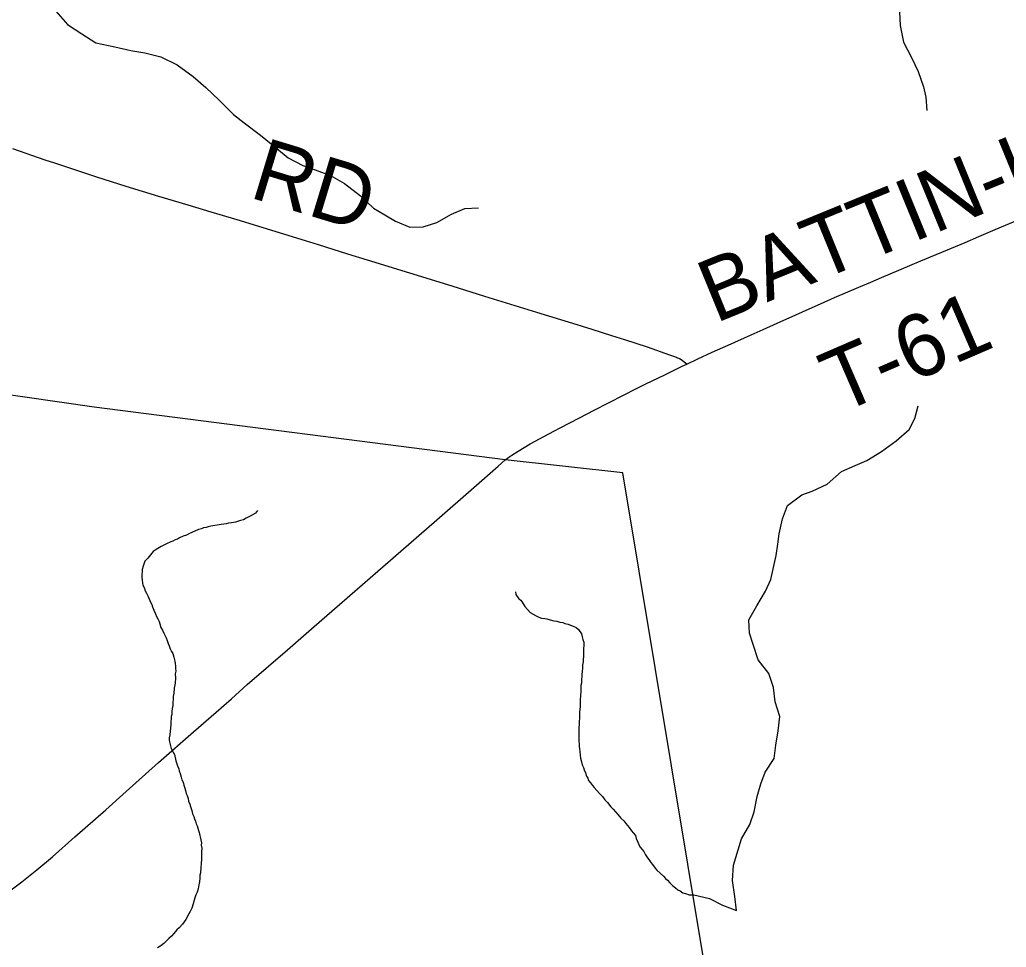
# Model space of a CAD drawing. Extents: x -19.5 to 44.1, y 0 to 22.
# Drawn here: x -14.727 to -13.829, y 6.591 to 7.436 of the extents above; entities that cross this region are included whole.
import ezdxf

# ---------------------------------------------------------------- set-up
doc = ezdxf.new("R2010")
doc.units = 0
for name, color, linetype in [('GM_X_County_Road', 7, 'Continuous'), ('GM_X_Minor_River', 7, 'Continuous'), ('GM_X_Township', 7, 'Continuous'), ('GM_X_Township_Road', 7, 'Continuous'), ('GM_X_Township_Road_Text', 7, 'Continuous')]:
    doc.layers.add(name, color=color, linetype=linetype)

msp = doc.modelspace()

# ---------------------------------------------------------------- linework, layer by layer
at = {"layer": 'GM_X_County_Road'}
msp.add_lwpolyline([(-14.7407, 6.63925), (-14.72466, 6.65093), (-14.71108, 6.66173), (-14.69691, 6.67379), (-14.67641, 6.69188), (-14.64848, 6.71653), (-14.62991, 6.73303), (-14.60029, 6.75953), (-14.56866, 6.78754), (-14.54805, 6.80551), (-14.53392, 6.81759), (-14.51956, 6.83042), (-14.48296, 6.86218), (-14.45863, 6.88343), (-14.43562, 6.90338), (-14.3868, 6.94571), (-14.347, 6.9804), (-14.31342, 7.00997), (-14.2913, 7.02939), (-14.28499, 7.03495)], dxfattribs=at)
at = {"layer": 'GM_X_Minor_River'}
for points in [[(-14.69382, 7.44333), (-14.68334, 7.43108), (-14.67016, 7.4226), (-14.65736, 7.4145)], [(-13.92594, 7.44273), (-13.92531, 7.4302), (-13.92242, 7.415), (-13.91496, 7.40126), (-13.90902, 7.3883), (-13.90422, 7.3746), (-13.90203, 7.36509), (-13.90101, 7.35294)], [(-14.65736, 7.4145), (-14.6401, 7.41099), (-14.62569, 7.4075), (-14.6128, 7.40547), (-14.59841, 7.40192), (-14.5833, 7.39456), (-14.56897, 7.3838), (-14.5573, 7.37382), (-14.54526, 7.36232), (-14.5321, 7.34929), (-14.52231, 7.3416), (-14.50761, 7.33046), (-14.49292, 7.31855), (-14.48237, 7.30972), (-14.46915, 7.30276), (-14.4578, 7.29885), (-14.4438, 7.29379), (-14.43097, 7.28645), (-14.41665, 7.27531), (-14.40461, 7.26419), (-14.39441, 7.25801), (-14.3846, 7.25223), (-14.37174, 7.24679), (-14.35959, 7.24705), (-14.34702, 7.2511), (-14.33366, 7.25855), (-14.32146, 7.26375), (-14.3093, 7.26439)], [(-14.11323, 6.6392), (-14.09906, 6.63563), (-14.08697, 6.62982), (-14.07449, 6.62477), (-14.07588, 6.63768), (-14.07802, 6.65211), (-14.07712, 6.66614), (-14.07281, 6.68013), (-14.06967, 6.68997), (-14.06233, 6.70317), (-14.05842, 6.71451), (-14.05562, 6.72852), (-14.05209, 6.74024), (-14.04819, 6.75083), (-14.0401, 6.76326), (-14.03846, 6.77539), (-14.03643, 6.78826), (-14.03478, 6.80152), (-14.03921, 6.81484), (-14.0406, 6.82776), (-14.04503, 6.8407), (-14.05478, 6.85293), (-14.0592, 6.86701), (-14.06251, 6.87729), (-14.06315, 6.88943), (-14.05581, 6.90226), (-14.04809, 6.91546), (-14.04305, 6.92603), (-14.03828, 6.94798), (-14.03666, 6.95821), (-14.03542, 6.96768), (-14.03263, 6.98131), (-14.02796, 6.9934), (-14.01495, 7.00314), (-14.00543, 7.00646), (-13.99169, 7.01277), (-13.97867, 7.0244), (-13.96647, 7.02998), (-13.95579, 7.03442), (-13.94242, 7.04264), (-13.92904, 7.05237), (-13.91716, 7.06249), (-13.91213, 7.07269), (-13.90898, 7.08404)], [(-14.5103, 6.98897), (-14.51224, 6.98634), (-14.51686, 6.98376), (-14.52069, 6.98193), (-14.523, 6.98044), (-14.52568, 6.97973), (-14.52836, 6.97902), (-14.53027, 6.97829), (-14.53218, 6.97794), (-14.53409, 6.97759), (-14.53676, 6.97726), (-14.53868, 6.97691), (-14.54097, 6.97657), (-14.54326, 6.97623), (-14.54517, 6.97588), (-14.54708, 6.97554), (-14.54899, 6.97519), (-14.5509, 6.97484), (-14.5528, 6.9745), (-14.5551, 6.97415), (-14.55701, 6.97343), (-14.5593, 6.97309), (-14.56122, 6.97236), (-14.56389, 6.97165), (-14.56735, 6.97019), (-14.57233, 6.96799), (-14.57502, 6.96652), (-14.57809, 6.96543), (-14.58116, 6.96396), (-14.58308, 6.96285), (-14.58538, 6.96213), (-14.5873, 6.96103), (-14.58922, 6.9603), (-14.59305, 6.95847), (-14.59497, 6.95774), (-14.59804, 6.95627), (-14.60112, 6.95442), (-14.60343, 6.95294), (-14.60536, 6.95146), (-14.60769, 6.94846), (-14.61003, 6.94546), (-14.61273, 6.94284), (-14.61353, 6.94095), (-14.61433, 6.93831), (-14.61515, 6.93528), (-14.61518, 6.933), (-14.6156, 6.93073), (-14.61565, 6.92807), (-14.6153, 6.92578), (-14.61497, 6.92274), (-14.61462, 6.92083), (-14.61351, 6.91891), (-14.61242, 6.91585), (-14.61132, 6.91355), (-14.60985, 6.91049), (-14.60764, 6.90551), (-14.60654, 6.90321), (-14.60581, 6.9013), (-14.60472, 6.89824), (-14.60325, 6.89479), (-14.60215, 6.8925), (-14.60105, 6.8902), (-14.59994, 6.8879), (-14.59922, 6.88561), (-14.59813, 6.88254), (-14.59665, 6.87986), (-14.59555, 6.87718), (-14.59444, 6.87488), (-14.59333, 6.87296), (-14.59261, 6.87067), (-14.59151, 6.86799), (-14.59079, 6.8657), (-14.58969, 6.86302), (-14.58859, 6.86072), (-14.58748, 6.8588), (-14.58639, 6.85536), (-14.58569, 6.85193), (-14.58535, 6.84964), (-14.585, 6.84736), (-14.58504, 6.84508), (-14.5847, 6.84279), (-14.58512, 6.84014), (-14.5848, 6.83671), (-14.58526, 6.83178), (-14.5861, 6.82724), (-14.58655, 6.82268), (-14.58699, 6.81965), (-14.58702, 6.81737), (-14.58746, 6.81396), (-14.58751, 6.8113), (-14.58793, 6.80865), (-14.58836, 6.80599), (-14.5884, 6.80333), (-14.58881, 6.80144), (-14.58885, 6.79916), (-14.58927, 6.79689), (-14.58931, 6.79423), (-14.59023, 6.78474), (-14.59066, 6.78209), (-14.59069, 6.78019), (-14.59034, 6.77829)], [(-14.27544, 6.91501), (-14.2751, 6.91235), (-14.2725, 6.9085), (-14.27061, 6.90733), (-14.2695, 6.90541), (-14.2669, 6.90156), (-14.26466, 6.89887), (-14.26204, 6.89616), (-14.2594, 6.89459), (-14.25676, 6.89303), (-14.25412, 6.89184), (-14.25184, 6.89104), (-14.2488, 6.89061), (-14.24691, 6.8902), (-14.24387, 6.88939), (-14.24046, 6.88857), (-14.2378, 6.88814), (-14.23515, 6.88734), (-14.23249, 6.88691), (-14.2306, 6.88612), (-14.22757, 6.88531), (-14.2253, 6.88451), (-14.22302, 6.88371), (-14.22038, 6.88252), (-14.21812, 6.88058), (-14.21552, 6.87674), (-14.21481, 6.87407), (-14.21409, 6.8714), (-14.21337, 6.8691), (-14.21342, 6.86606), (-14.21347, 6.86302), (-14.21352, 6.85961), (-14.21356, 6.85771), (-14.21359, 6.85581), (-14.21401, 6.85353), (-14.21405, 6.85125), (-14.21448, 6.84822), (-14.21453, 6.84518), (-14.21495, 6.84253), (-14.215, 6.83949), (-14.21503, 6.83759), (-14.21545, 6.83569), (-14.21551, 6.8319), (-14.21593, 6.82962), (-14.21596, 6.82772), (-14.216, 6.82544), (-14.21603, 6.82354), (-14.21645, 6.82127), (-14.21648, 6.81937), (-14.21651, 6.81747), (-14.21654, 6.81557), (-14.21659, 6.81253), (-14.21663, 6.81025), (-14.21705, 6.80798), (-14.21709, 6.80532), (-14.21713, 6.80304), (-14.21718, 6.8), (-14.21761, 6.79697), (-14.21775, 6.78861), (-14.2178, 6.78595), (-14.21785, 6.78253), (-14.21788, 6.78063), (-14.21792, 6.77873), (-14.21757, 6.77683), (-14.21761, 6.77417), (-14.21727, 6.77188), (-14.21693, 6.7696), (-14.2166, 6.76617), (-14.21627, 6.76351), (-14.21556, 6.76007), (-14.21484, 6.7574), (-14.21374, 6.7551), (-14.21302, 6.75281), (-14.21192, 6.75013), (-14.21083, 6.74707), (-14.20972, 6.74515), (-14.20899, 6.74324), (-14.20712, 6.74093), (-14.20526, 6.73862), (-14.20376, 6.73669), (-14.20152, 6.73399), (-14.19891, 6.73129), (-14.19628, 6.72858), (-14.19405, 6.7255), (-14.1918, 6.72318), (-14.18882, 6.71933), (-14.18658, 6.71701), (-14.18246, 6.71238), (-14.17948, 6.70891), (-14.17685, 6.70659), (-14.17499, 6.7039), (-14.172, 6.70042), (-14.16977, 6.69734), (-14.16828, 6.69542), (-14.16641, 6.69311), (-14.16569, 6.69043), (-14.16423, 6.68699), (-14.16239, 6.68278), (-14.16015, 6.68046), (-14.15866, 6.67853), (-14.15718, 6.67547)], [(-14.59034, 6.77829), (-14.58963, 6.77485), (-14.58892, 6.77218), (-14.58706, 6.76911), (-14.58596, 6.76681), (-14.58453, 6.76108), (-14.58308, 6.7565), (-14.58199, 6.75382), (-14.58164, 6.75191), (-14.58054, 6.74962), (-14.57983, 6.74618), (-14.57911, 6.74389), (-14.578, 6.74159), (-14.57729, 6.73892), (-14.57657, 6.73625), (-14.57584, 6.73395), (-14.57513, 6.73128), (-14.5744, 6.72937), (-14.5733, 6.72669), (-14.57296, 6.7244), (-14.57186, 6.72172), (-14.57114, 6.71943), (-14.57005, 6.71599), (-14.56934, 6.71294), (-14.56824, 6.71026), (-14.56751, 6.70835), (-14.56679, 6.70606), (-14.56607, 6.70376), (-14.56534, 6.70185), (-14.56461, 6.69994), (-14.56388, 6.69765), (-14.56353, 6.69574), (-14.56174, 6.68925), (-14.5614, 6.68658), (-14.56144, 6.6843), (-14.5611, 6.68164), (-14.56116, 6.67822), (-14.5612, 6.67594), (-14.56124, 6.67366), (-14.56127, 6.67138), (-14.56171, 6.66797), (-14.56178, 6.66379), (-14.56224, 6.65924), (-14.56266, 6.65696), (-14.5627, 6.65431), (-14.56314, 6.65089), (-14.56356, 6.64824), (-14.56439, 6.64445), (-14.5652, 6.64143), (-14.56638, 6.63917), (-14.56719, 6.63652), (-14.5688, 6.63085), (-14.57001, 6.62707), (-14.57158, 6.62406), (-14.57276, 6.62179), (-14.57551, 6.61652), (-14.57863, 6.6124), (-14.58173, 6.60903), (-14.58367, 6.60716), (-14.58639, 6.60379), (-14.58871, 6.60155), (-14.59103, 6.59931), (-14.59335, 6.59707), (-14.59568, 6.59483), (-14.59838, 6.59259), (-14.60146, 6.59075)], [(-14.15718, 6.67547), (-14.15607, 6.67355), (-14.15346, 6.67046), (-14.15235, 6.66854), (-14.15086, 6.66662), (-14.14824, 6.66353), (-14.14675, 6.66161), (-14.14375, 6.6589), (-14.14075, 6.65619), (-14.13888, 6.65387), (-14.13701, 6.65232), (-14.13514, 6.65001), (-14.13251, 6.64768), (-14.12989, 6.64536), (-14.12763, 6.6438), (-14.12574, 6.64263), (-14.1231, 6.64106), (-14.12083, 6.64026), (-14.11743, 6.63906), (-14.11323, 6.6392)]]:
    msp.add_lwpolyline(points, dxfattribs=at)
at = {"layer": 'GM_X_Township'}
msp.add_lwpolyline([(-12.89135, 6.37944), (-13.11367, 6.40414), (-13.35833, 6.42942), (-13.44114, 6.43455), (-13.5998, 6.44439), (-14.08907, 6.4899), (-14.17771, 7.02314), (-14.28499, 7.03495), (-14.65899, 7.08304), (-15.5678, 7.21413), (-15.56001, 7.19629), (-16.11933, 6.86064), (-16.1939, 6.81589), (-16.21334, 6.81208), (-16.897, 6.44106), (-17.1473, 6.30523)], dxfattribs=at)
at = {"layer": 'GM_X_Township_Road'}
for points in [[(-14.1197, 7.12209), (-14.12199, 7.12392), (-14.1239, 7.12543), (-14.12637, 7.12698), (-14.13053, 7.12871), (-14.1349, 7.13035), (-14.15543, 7.13741), (-14.17604, 7.1442), (-14.18784, 7.14795), (-14.20562, 7.1535), (-14.22341, 7.15901), (-14.25603, 7.16907), (-14.30348, 7.18378), (-14.3331, 7.19297), (-14.41021, 7.21686), (-14.42802, 7.2223), (-14.45466, 7.2306), (-14.46652, 7.23424), (-14.52885, 7.2533), (-14.55261, 7.26054), (-14.57342, 7.26676), (-14.60016, 7.27476), (-14.62984, 7.28382), (-14.65651, 7.29219), (-14.6948, 7.30493), (-14.70363, 7.30789), (-14.73287, 7.31814)], [(-14.1197, 7.12209), (-14.10969, 7.1268), (-14.09641, 7.13292), (-14.08183, 7.13952), (-14.06094, 7.14889), (-14.05017, 7.15354), (-14.03726, 7.1593), (-14.02036, 7.16691), (-14.0081, 7.17239), (-13.9978, 7.17712), (-13.98507, 7.1827), (-13.96316, 7.19207), (-13.95211, 7.19681), (-13.94236, 7.20099), (-13.92648, 7.20756), (-13.90652, 7.21613), (-13.87866, 7.22764), (-13.86622, 7.23284), (-13.85378, 7.23832), (-13.83891, 7.24463), (-13.81658, 7.25414)], [(-14.28499, 7.03495), (-14.28147, 7.03748), (-14.27873, 7.03927), (-14.2731, 7.04282), (-14.26201, 7.04967), (-14.25362, 7.05427), (-14.24062, 7.06114), (-14.23477, 7.06427), (-14.21731, 7.07331), (-14.20384, 7.08009), (-14.19085, 7.08678), (-14.17664, 7.0942), (-14.166, 7.09964), (-14.15677, 7.10414), (-14.1395, 7.11249), (-14.12371, 7.12021), (-14.1197, 7.12209)]]:
    msp.add_lwpolyline(points, dxfattribs=at)

# ---------------------------------------------------------------- texts
at = {"layer": 'GM_X_Township_Road_Text'}
for s, height, rotation, p in [('BATTIN-HOWELL', 0.0568182, 22.28066, (-14.09363, 7.15901)), ('RD', 0.056818, 343.11363, (-14.51906, 7.27426)), ('T-61', 0.056818, 23.4158, (-13.98102, 7.07639))]:
    msp.add_text(s, height=height, rotation=rotation, dxfattribs=at).set_placement(p)

doc.saveas('drawing.dxf')
